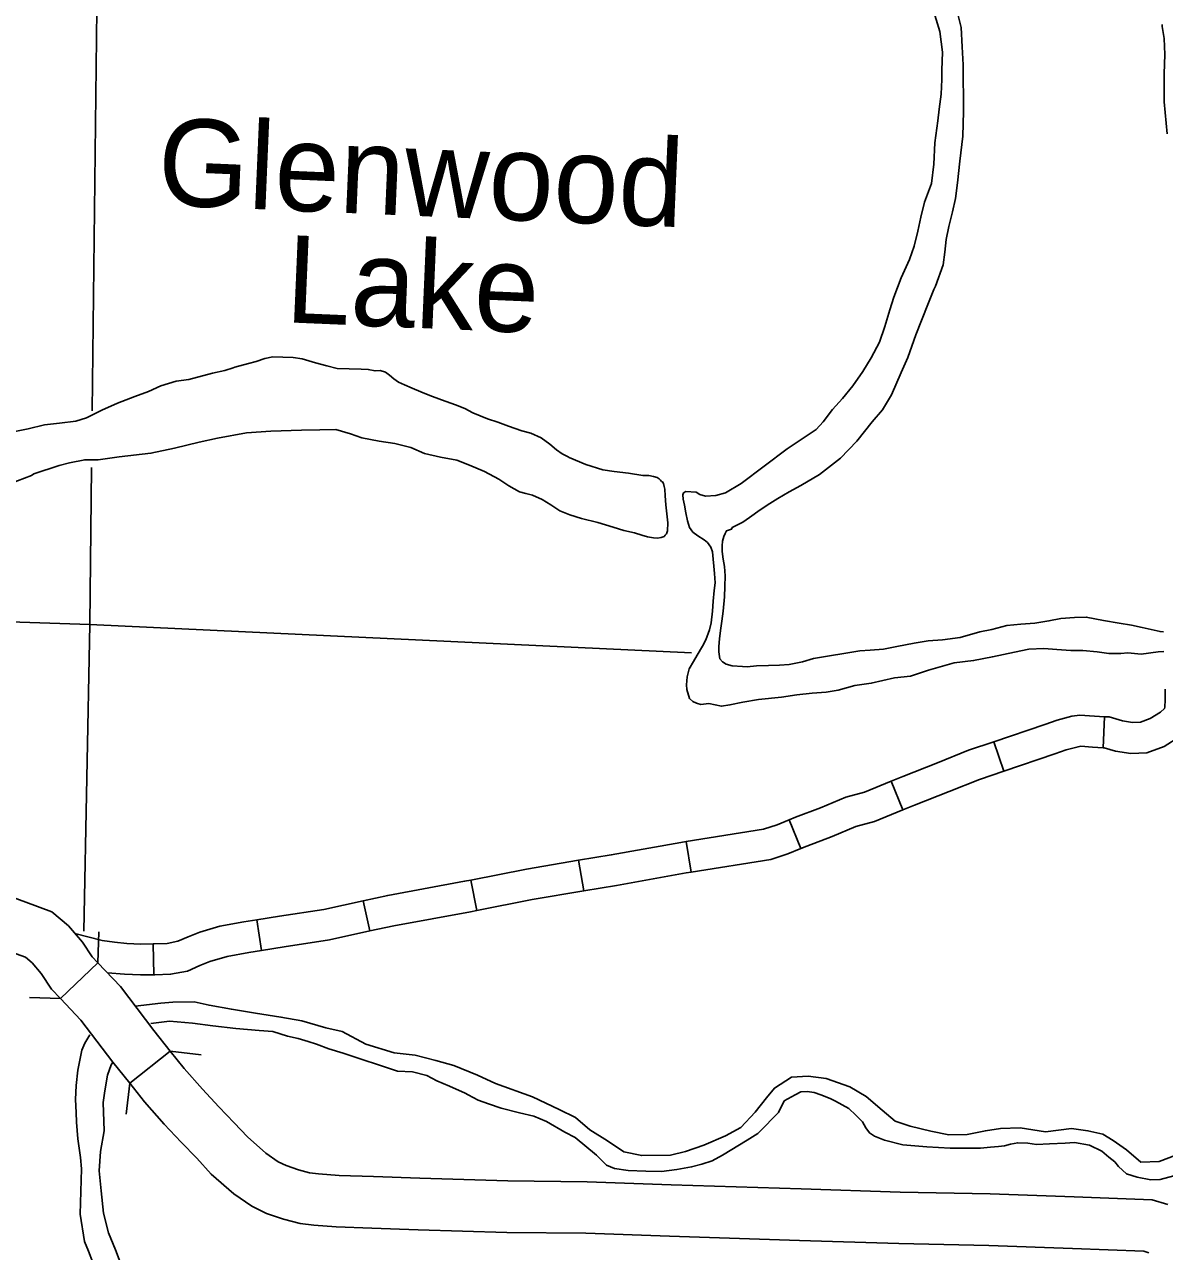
# Model space of a CAD drawing. Extents: x 1196286 to 1268366, y 2040822 to 2082115.
# Drawn here: x 1230571 to 1232639, y 2054453 to 2056680 of the extents above; entities that cross this region are included whole.
import ezdxf

# ---------------------------------------------------------------- set-up
doc = ezdxf.new("R2010")
doc.units = 0
for name, color, linetype in [('60', 7, 'Continuous'), ('61', 7, 'Continuous'), ('62', 7, 'Continuous'), ('Level 76', 7, 'Continuous'), ('Level 87', 7, 'Continuous')]:
    doc.layers.add(name, color=color, linetype=linetype)

msp = doc.modelspace()

# ---------------------------------------------------------------- linework, layer by layer
at = {"layer": '60'}
for points in [[(1230712, 2057540.5), (1230694.1, 2055979.1)], [(1230692.9, 2055875.9), (1230689.6, 2055591.4), (1230679, 2055034.8)], [(1230218, 2055606.8), (1230689.6, 2055591.4), (1231781.1, 2055540)]]:
    msp.add_lwpolyline(points, dxfattribs=at)
at = {"layer": '61'}
for p, q in [((1232528, 2055367.5), (1232530.4, 2055423.7)), ((1232347.7, 2055325.1), (1232329.7, 2055378.4)), ((1232164.7, 2055254.7), (1232143.2, 2055306.7)), ((1231979.6, 2055184.5), (1231958.4, 2055236.6)), ((1231780.5, 2055141.9), (1231771.6, 2055197.4)), ((1231585.7, 2055107.7), (1231576.4, 2055163.2)), ((1231391.7, 2055072.2), (1231380.8, 2055127.4)), ((1231197.9, 2055035), (1231185.9, 2055089.9)), ((1231001.4, 2054999.6), (1230992.7, 2055055.2)), ((1230805.8, 2054955.4), (1230804.9, 2055011.7))]:
    msp.add_line(p, q, dxfattribs=at)
for points in [[(1232634.9, 2056679.9), (1232635.1, 2056676.4), (1232638.5, 2056654.6), (1232639.5, 2056625.8), (1232638.6, 2056590.3), (1232638.3, 2056539.8), (1232643.7, 2056481.6)], [(1232528, 2055367.5), (1232529.4, 2055367.4), (1232550.4, 2055361.4), (1232577.7, 2055356.9), (1232607.1, 2055358.1), (1232638.3, 2055369.8), (1232666.7, 2055387.6), (1232687.7, 2055407.6), (1232695.6, 2055430.8), (1232696.6, 2055453.1), (1232696.5, 2055474)], [(1232530.4, 2055423.7), (1232538.5, 2055423.3), (1232562.8, 2055416.3), (1232581.1, 2055413.3), (1232595.8, 2055413.9), (1232613.2, 2055420.5), (1232632, 2055432.3), (1232639, 2055438.9), (1232639.8, 2055441.3), (1232640.3, 2055454.2), (1232640.3, 2055473.8)], [(1232329.7, 2055378.4), (1232421.9, 2055409.7), (1232444.2, 2055417.4), (1232470.9, 2055424.5), (1232485.3, 2055426.7), (1232511.8, 2055424.5), (1232530.4, 2055423.7)], [(1232143.2, 2055306.7), (1232164.7, 2055315.6), (1232227.4, 2055340.4), (1232283.8, 2055362.8), (1232329.7, 2055378.4)], [(1232347.7, 2055325.1), (1232440.1, 2055356.5), (1232460.6, 2055363.6), (1232482.3, 2055369.3), (1232487.2, 2055370.1), (1232508.3, 2055368.3), (1232528, 2055367.5)], [(1232164.7, 2055254.7), (1232185.8, 2055263.5), (1232248.2, 2055288.1), (1232303.3, 2055310), (1232347.7, 2055325.1)], [(1231958.4, 2055236.6), (1231969.9, 2055241.3), (1232015.3, 2055258.7), (1232061.2, 2055277.8), (1232095.1, 2055286.8), (1232143.2, 2055306.7)], [(1231979.6, 2055184.5), (1231990.6, 2055189), (1232036.2, 2055206.5), (1232079.3, 2055224.4), (1232113.1, 2055233.4), (1232164.7, 2055254.7)], [(1231771.6, 2055197.4), (1231911.9, 2055219.8), (1231936.7, 2055227.8), (1231958.4, 2055236.6)], [(1231576.4, 2055163.2), (1231635.5, 2055173.1), (1231761.8, 2055195.8), (1231771.6, 2055197.4)], [(1231780.5, 2055141.9), (1231925.1, 2055164.9), (1231956, 2055174.9), (1231979.6, 2055184.5)], [(1231380.8, 2055127.4), (1231482.1, 2055147.4), (1231576.4, 2055163.2)], [(1231585.7, 2055107.7), (1231645.1, 2055117.7), (1231771.2, 2055140.4), (1231780.5, 2055141.9)], [(1231185.9, 2055089.9), (1231230.3, 2055099.6), (1231369.5, 2055125.2), (1231380.8, 2055127.4)], [(1230992.7, 2055055.2), (1231033.6, 2055061.6), (1231114.2, 2055074.2), (1231185.9, 2055089.9)], [(1231391.7, 2055072.2), (1231492.2, 2055092), (1231585.7, 2055107.7)], [(1231197.9, 2055035), (1231241.4, 2055044.5), (1231380.1, 2055069.9), (1231391.7, 2055072.2)], [(1230804.9, 2055011.7), (1230806.6, 2055011.7), (1230830, 2055012.4), (1230849.7, 2055016.3), (1230867.9, 2055024.4), (1230889.5, 2055032.7), (1230925.4, 2055043.5), (1230969, 2055051.5), (1230992.7, 2055055.2)], [(1230662.9, 2055030.5), (1230711.9, 2055017.9), (1230734.3, 2055014.5), (1230756.7, 2055012.4), (1230782.5, 2055011.3), (1230804.9, 2055011.7)], [(1231001.4, 2054999.6), (1231042.3, 2055006), (1231124.6, 2055018.9), (1231197.9, 2055035)], [(1230805.8, 2054955.4), (1230807.9, 2054955.5), (1230836.3, 2054956.3), (1230866.8, 2054962.3), (1230889.4, 2054972.4), (1230907.7, 2054979.4), (1230938.7, 2054988.7), (1230978.5, 2054996.1), (1231001.4, 2054999.6)], [(1230721.6, 2054959.2), (1230753, 2054956.3), (1230781.8, 2054955.1), (1230805.8, 2054955.4)]]:
    msp.add_lwpolyline(points, dxfattribs=at)
at = {"layer": '62'}
for points in [[(1231771, 2055832.5), (1231789.7, 2055831.5), (1231796, 2055827.3), (1231806.8, 2055823.8), (1231825.2, 2055825.4), (1231842.8, 2055830), (1231871.2, 2055846.9), (1231954.8, 2055909.7), (1232007, 2055945.1), (1232019.9, 2055959.2), (1232036.7, 2055981.1), (1232055.3, 2056001.2), (1232073.6, 2056024.3), (1232091.6, 2056050.3), (1232107.2, 2056074.9), (1232122.2, 2056103.7), (1232131.6, 2056131.8), (1232141, 2056162.5), (1232148.1, 2056184.9), (1232161.7, 2056220.1), (1232176.3, 2056253.7), (1232184.9, 2056277.7), (1232191.6, 2056304.7), (1232197.2, 2056330.5), (1232204, 2056357.5), (1232216.4, 2056391.2), (1232220.6, 2056426.8), (1232222.3, 2056465.2), (1232227.7, 2056505), (1232230.2, 2056526.4), (1232234, 2056553.8), (1232235.1, 2056580.1), (1232235.3, 2056597.4), (1232236.1, 2056629.7), (1232231.4, 2056667.4), (1232218.1, 2056710.8)], [(1232264, 2056698.9), (1232270.1, 2056674.7), (1232271.8, 2056639.7), (1232273.6, 2056607), (1232274.4, 2056522), (1232273, 2056477.6), (1232267.9, 2056431.8), (1232263.6, 2056392.4), (1232259.9, 2056364.3), (1232254.7, 2056340.3), (1232247.9, 2056313.7), (1232242.8, 2056290), (1232240.9, 2056266.7), (1232237.6, 2056243.9), (1232224, 2056205.3), (1232220.9, 2056199), (1232210.9, 2056175), (1232198.4, 2056142.9), (1232188, 2056116.7), (1232173.6, 2056075.9), (1232161.2, 2056048.6), (1232143.8, 2056007.9), (1232127.3, 2055981), (1232109, 2055958.7), (1232080.8, 2055923.7), (1232051.2, 2055892.9), (1232013.4, 2055863.4), (1231979.7, 2055843.2), (1231958.2, 2055832.2), (1231937.5, 2055820.1), (1231923.1, 2055810.5), (1231905.7, 2055799.4), (1231886.4, 2055785.4), (1231874, 2055776.9), (1231855.1, 2055767.1), (1231853.9, 2055764.4), (1231844.9, 2055761.2), (1231842.2, 2055756.3), (1231839.5, 2055750.7), (1231837.2, 2055742.5), (1231836.7, 2055734.2), (1231836.9, 2055723.7), (1231838.6, 2055709.7), (1231840.7, 2055696.6), (1231842.3, 2055679.6), (1231841.7, 2055660.1), (1231841, 2055641.3), (1231838.4, 2055615.4), (1231836.3, 2055597.3), (1231833.5, 2055580.5), (1231832.1, 2055565.1), (1231830.8, 2055551.5), (1231830.7, 2055541.4), (1231832.8, 2055528.9), (1231837.2, 2055523.2), (1231844.3, 2055519.4), (1231854.7, 2055516.2), (1231873.8, 2055515.2), (1231882, 2055514.4), (1231898.9, 2055516.4), (1231921, 2055516.8), (1231940.5, 2055517.3), (1231958.1, 2055518.6), (1231982.5, 2055523.5), (1232002.5, 2055529.2), (1232086.6, 2055543.1), (1232105.3, 2055544.7), (1232129.3, 2055546.6), (1232153.3, 2055551.2)], [(1231260.8, 2056026.1), (1231249.6, 2056031.2), (1231241.4, 2056036.9), (1231233.3, 2056043.8), (1231225.9, 2056048.8), (1231216.5, 2056051.9), (1231207.2, 2056051.3), (1231194.8, 2056054.1), (1231182.1, 2056054.3), (1231138.7, 2056056), (1231119.6, 2056060.8), (1231099.1, 2056066.3), (1231075.2, 2056073.1), (1231058.4, 2056075.9), (1231039.7, 2056076.2), (1231021.7, 2056076.8), (1231007.1, 2056074), (1230991.6, 2056068.6), (1230977.4, 2056064.6), (1230952.9, 2056058.2), (1230949.9, 2056056.8), (1230934.9, 2056052.4), (1230912.3, 2056047.1), (1230869.5, 2056035.7), (1230846.6, 2056033), (1230818.7, 2056024.3), (1230796.1, 2056013.8), (1230771.3, 2056004.7), (1230740, 2055993.1), (1230711.4, 2055980), (1230683.5, 2055966.4), (1230664.3, 2055959.9), (1230635, 2055956.6), (1230607.6, 2055953.2), (1230577.9, 2055946.5), (1230550.9, 2055940.8)], [(1230545.9, 2055847.3), (1230584.3, 2055861.4), (1230588.4, 2055864.3), (1230634.3, 2055879.5), (1230653.1, 2055884.5), (1230680.6, 2055890.1), (1230704.9, 2055889.8), (1230743.2, 2055895.3), (1230800.6, 2055902), (1230843.4, 2055911.2), (1230888.1, 2055921.9), (1230921.2, 2055929.3), (1230973.8, 2055938.7), (1231018.4, 2055942.2), (1231073.5, 2055943.7), (1231107.2, 2055944.4), (1231136.1, 2055945.1), (1231162.5, 2055936.9), (1231183.4, 2055930.2), (1231214.4, 2055924.1), (1231243.2, 2055919.6), (1231272.3, 2055912.4), (1231296.9, 2055901.5), (1231326, 2055894.7), (1231355.2, 2055889.1), (1231378.7, 2055880.5), (1231405.9, 2055868.8), (1231431.9, 2055854.9), (1231449.7, 2055842.6), (1231469, 2055832.2), (1231480.6, 2055829), (1231492.9, 2055825.9), (1231510, 2055818.1), (1231526, 2055808.1), (1231542.4, 2055797.7), (1231560.6, 2055789.9), (1231581.9, 2055783.6), (1231611.4, 2055776.5), (1231639, 2055767.8), (1231658.4, 2055761.9), (1231677.8, 2055757.5), (1231690.8, 2055753.5), (1231701.3, 2055750), (1231712.1, 2055748.4), (1231719.2, 2055747.9), (1231726.4, 2055748.9), (1231731.3, 2055751.1), (1231733.5, 2055753.3), (1231735.5, 2055755.9), (1231737.8, 2055761.2), (1231738, 2055775.4), (1231734.3, 2055808.6), (1231733.4, 2055824.4), (1231732.8, 2055836.8), (1231731.7, 2055841.7), (1231730.3, 2055847), (1231728.5, 2055850), (1231727, 2055850.8), (1231725.2, 2055853.1), (1231722.6, 2055855.4), (1231718.9, 2055857.7), (1231712.5, 2055860), (1231703.5, 2055861.3), (1231692.7, 2055861.4), (1231666.9, 2055865.6), (1231640.7, 2055868.9), (1231620.2, 2055871.8), (1231589.2, 2055881.7), (1231559.4, 2055894.5), (1231557.2, 2055895.3), (1231546.4, 2055900.7), (1231536.4, 2055908.4), (1231524.1, 2055918.3), (1231508.6, 2055930.2), (1231490, 2055938.3), (1231473.2, 2055942.7), (1231449.3, 2055950.9), (1231429.9, 2055958.3), (1231411.3, 2055964.2), (1231384.4, 2055975.5), (1231369.9, 2055982.9), (1231353.2, 2055989.9), (1231327.8, 2055998.9), (1231306.6, 2056006.7), (1231290.2, 2056013.3), (1231274.5, 2056019.9), (1231260.8, 2056026.1)], [(1232637.7, 2055542.4), (1232627.8, 2055541.6), (1232596.7, 2055537.2), (1232572.7, 2055539.8), (1232560, 2055538.4), (1232537.9, 2055538.8), (1232516.9, 2055541.3), (1232490.7, 2055543.9), (1232469, 2055543.8), (1232443.6, 2055545.7), (1232420.4, 2055547.5), (1232393, 2055546.4), (1232366.7, 2055540.7), (1232326.9, 2055532.6), (1232292.7, 2055525.6), (1232257.8, 2055521.6), (1232210.8, 2055508.3), (1232178.1, 2055497.1), (1232149.6, 2055494.5), (1232107.1, 2055484.5), (1232077.1, 2055480.4), (1232047, 2055472.2), (1232025.6, 2055468.4), (1231999.7, 2055466.8), (1231972.4, 2055463.8), (1231944.2, 2055459), (1231902.6, 2055455), (1231874.4, 2055450.5), (1231850.7, 2055445.2), (1231835.4, 2055442.8), (1231812.6, 2055447.6), (1231798.3, 2055445.9), (1231790.5, 2055448.3), (1231783.4, 2055451.4), (1231777.5, 2055457.1), (1231772.5, 2055473), (1231771.8, 2055481.7), (1231773.1, 2055495.9), (1231777.1, 2055510.9), (1231784.8, 2055524), (1231791.3, 2055535.5), (1231800.9, 2055551.6), (1231807, 2055563.2), (1231813.6, 2055581.5), (1231816.8, 2055593.9), (1231819, 2055615.6), (1231820.3, 2055633.3), (1231822.5, 2055652.8), (1231823.8, 2055666.7), (1231822.9, 2055684), (1231819.3, 2055722.8), (1231816, 2055731.5), (1231810.2, 2055739.9), (1231803.9, 2055744.5), (1231792.7, 2055752.1), (1231783.8, 2055758.6), (1231777.6, 2055767.4), (1231773.6, 2055779.1), (1231770.8, 2055793.8), (1231768.7, 2055807.7), (1231766.3, 2055818.3), (1231765.6, 2055826.6), (1231766.4, 2055830), (1231771, 2055832.5)], [(1232153.3, 2055551.2), (1232185.3, 2055557.2), (1232210.4, 2055561.7), (1232236.3, 2055563.6), (1232268.6, 2055567.3), (1232304.3, 2055578.1), (1232325.7, 2055581.9), (1232353.1, 2055589.4), (1232378.6, 2055591.7), (1232403.8, 2055593.6), (1232429.3, 2055597.8), (1232451.1, 2055602), (1232476.1, 2055603.6), (1232497.2, 2055604.7), (1232528.2, 2055598.7), (1232557, 2055593.4), (1232579, 2055590.1), (1232598.8, 2055585.6), (1232630.9, 2055578.4), (1232637.4, 2055577.8)], [(1232659.8, 2054628.4), (1232629.2, 2054616.5), (1232596.3, 2054615.2), (1232569.9, 2054637.6), (1232545.9, 2054654.6), (1232527.3, 2054666), (1232500.2, 2054672.5), (1232470.2, 2054676.4), (1232423.5, 2054670.4), (1232377.2, 2054677.7), (1232341.6, 2054676.6), (1232314.1, 2054672.5), (1232280.9, 2054665.9), (1232248, 2054664.7), (1232215.5, 2054671.4), (1232177.6, 2054681), (1232150.6, 2054690.1), (1232126.8, 2054709.7), (1232097.8, 2054734.8), (1232068.4, 2054752), (1232025.2, 2054767.2), (1231992.6, 2054771.2), (1231962.4, 2054769.9), (1231931.4, 2054749.9), (1231917, 2054732), (1231896.7, 2054706.3), (1231870.9, 2054678.1), (1231842.9, 2054663.4), (1231803.8, 2054646.5), (1231770.5, 2054634.6), (1231742.8, 2054627.9), (1231690.8, 2054627.4), (1231658.2, 2054634.1), (1231629, 2054654), (1231597, 2054673.9), (1231570.6, 2054696.3), (1231541.1, 2054710.9), (1231492.8, 2054734.2), (1231425.4, 2054758.3), (1231393.2, 2054773), (1231350.2, 2054790.8), (1231317.7, 2054800.1), (1231279.8, 2054809.7), (1231241.7, 2054814), (1231190.3, 2054829.5), (1231147.5, 2054852.6), (1231117.7, 2054859.1), (1231074.4, 2054871.6), (1231036.4, 2054878.6), (1230990.2, 2054885.9), (1230946.7, 2054893), (1230906, 2054900.1), (1230878.9, 2054906.6), (1230840.5, 2054905.6), (1230818.5, 2054903.8), (1230772.3, 2054898.7)], [(1230800.5, 2054866.9), (1230834.6, 2054871.1), (1230875.8, 2054867.7), (1230912.8, 2054862.9), (1230954.9, 2054857.8), (1230997, 2054854.3), (1231022, 2054852.4), (1231048.2, 2054844), (1231067.9, 2054839.7), (1231085.8, 2054834.2), (1231100.7, 2054829.5), (1231123.1, 2054821.3), (1231149.6, 2054813), (1231247.6, 2054780.4), (1231275, 2054779.3), (1231301.1, 2054772.6), (1231319.3, 2054762.9), (1231342.1, 2054753.6), (1231370.7, 2054740.4), (1231375.9, 2054737.3), (1231394.2, 2054728), (1231412.8, 2054721), (1231435.9, 2054713.5), (1231469.1, 2054705.2), (1231494.9, 2054698.8), (1231518, 2054689.5), (1231551.1, 2054669.8), (1231570, 2054660.1), (1231608.6, 2054628), (1231627, 2054610.1), (1231641.2, 2054603.9), (1231666.2, 2054600.5), (1231698.4, 2054599.3), (1231726.5, 2054598.6), (1231754.3, 2054601.9), (1231781.3, 2054606.8), (1231799.7, 2054611.5), (1231818.9, 2054618), (1231837.1, 2054628.2), (1231882.4, 2054655.1), (1231901.3, 2054667.2), (1231915.3, 2054681.3), (1231927.5, 2054694.3), (1231938.9, 2054705.4), (1231949.3, 2054726.7), (1231969.3, 2054737.3), (1231979.5, 2054742.8), (1231991.1, 2054743.8), (1232003.4, 2054742.1), (1232015.7, 2054737.8), (1232032.9, 2054731.2), (1232042.2, 2054726.2), (1232066.7, 2054712.7), (1232079.3, 2054700.8), (1232091.1, 2054688.3), (1232097.3, 2054677.7), (1232103.9, 2054668.5), (1232113.2, 2054662.4), (1232131.1, 2054655.4), (1232164.7, 2054647), (1232208.1, 2054643), (1232250, 2054640.6), (1232305.5, 2054640.6), (1232323.5, 2054642.6), (1232337.7, 2054643.9), (1232349, 2054644.8), (1232359.9, 2054648.1), (1232373, 2054650.5), (1232391, 2054649.9), (1232407.1, 2054647.4), (1232430.7, 2054648.6), (1232458.8, 2054650.1), (1232475.7, 2054651), (1232502.9, 2054646.1), (1232525.3, 2054635.3), (1232538.2, 2054624.5), (1232548.9, 2054615.9)], [(1230703.3, 2054412.7), (1230687.7, 2054453.9), (1230680.1, 2054471.7), (1230672.1, 2054521), (1230674.8, 2054603), (1230672.8, 2054623.7), (1230668, 2054657.6), (1230665.4, 2054687.7), (1230665.3, 2054705.8), (1230664.1, 2054729.1), (1230664.8, 2054754.3), (1230667.8, 2054782.1), (1230671.4, 2054800.5), (1230675.4, 2054818.5), (1230680.8, 2054831.5), (1230689.6, 2054846.6)], [(1230730.8, 2054795.7), (1230728.6, 2054791.8), (1230721.6, 2054773.4), (1230716.8, 2054744.9), (1230714.2, 2054723.9), (1230715.8, 2054672.4), (1230708.9, 2054634.9), (1230706.9, 2054599.5), (1230710.6, 2054563.4), (1230714.5, 2054523.1), (1230723.4, 2054486.9), (1230736.4, 2054456.2), (1230748.7, 2054424.1), (1230761.1, 2054396.1), (1230779.1, 2054370.3), (1230787.5, 2054352.1), (1230797.5, 2054316.2)], [(1232548.9, 2054615.9), (1232555.5, 2054607.6), (1232570.3, 2054594.4), (1232589.5, 2054588.1), (1232614.5, 2054583.1), (1232631.5, 2054583.9), (1232656.1, 2054590.7), (1232677.5, 2054597.7), (1232701, 2054610.6)]]:
    msp.add_lwpolyline(points, dxfattribs=at)
at = {"layer": 'Level 76'}
for points in [[(1230705.9, 2055033.5), (1230704.4, 2054977.2)], [(1230636.4, 2054912.7), (1230580.2, 2054914.2)], [(1230835.7, 2054816.8), (1230891.5, 2054810.3)], [(1230755.7, 2054702.8), (1230762.2, 2054758.7)]]:
    msp.add_lwpolyline(points, dxfattribs=at)
at = {"layer": 'Level 87'}
msp.add_line((1230835.7, 2054816.8), (1230835.7, 2054816.8), dxfattribs=at)
for points in [[(1230541.3, 2054999.1), (1230573, 2054987.5), (1230585, 2054977.3), (1230601.7, 2054957.9), (1230620.6, 2054929.3), (1230636.4, 2054912.7), (1230704.4, 2054977.2), (1230694.3, 2054987.9), (1230676.5, 2055014.7), (1230651.2, 2055044), (1230621, 2055069.8), (1230573.6, 2055087.1), (1230452.1, 2055131.8)], [(1230704.4, 2054977.2), (1230745.3, 2054934.1), (1230805.8, 2054854.5), (1230835.7, 2054816.8)], [(1230636.4, 2054912.7), (1230673.8, 2054873.3), (1230731.8, 2054797.1), (1230762.2, 2054758.7)], [(1230835.7, 2054816.8), (1230762.2, 2054758.7)], [(1232645.4, 2054538.4), (1232616.4, 2054546.8), (1232475.5, 2054552.3), (1232323, 2054557.8), (1232159.6, 2054561.2), (1231979.8, 2054566.7), (1231744.4, 2054574.5), (1231591.9, 2054580), (1231448.3, 2054581.6), (1231288.6, 2054586.1), (1231204.6, 2054589.1), (1231142, 2054591.5), (1231104.6, 2054594.5), (1231088.3, 2054596.2), (1231068.3, 2054601.6), (1231045.7, 2054609.2), (1231031.3, 2054616.3), (1231008.9, 2054631.9), (1230975.6, 2054661.1), (1230951.9, 2054686.7), (1230923.8, 2054716.1), (1230894.1, 2054747.9), (1230860.7, 2054785.3), (1230835.7, 2054816.8)], [(1230762.2, 2054758.7), (1230788.9, 2054724.9), (1230824.9, 2054684.6), (1230855.7, 2054651.7), (1230883.7, 2054622.4), (1230910.2, 2054593.8), (1230951, 2054558.1), (1230983.5, 2054535.3), (1231010, 2054522.3), (1231041.1, 2054511.8), (1231071.1, 2054503.8), (1231095.9, 2054501.2), (1231136.4, 2054497.9), (1231201.1, 2054495.4), (1231285.6, 2054492.4), (1231446.4, 2054487.9), (1231589.7, 2054486.3), (1231741.2, 2054480.8), (1231976.8, 2054473), (1232157.2, 2054467.5), (1232320.4, 2054464.1), (1232471.9, 2054458.6), (1232601.3, 2054453.6), (1232610.4, 2054451)]]:
    msp.add_lwpolyline(points, dxfattribs=at)

# ---------------------------------------------------------------- texts
at = {"layer": '62'}
for s, p in [('Glenwood', (1230810.8, 2056352.8)), ('Lake', (1231042.9, 2056139.7))]:
    msp.add_text(s, height=158.4, rotation=357.548, dxfattribs=at).set_placement(p)

doc.saveas('drawing.dxf')
